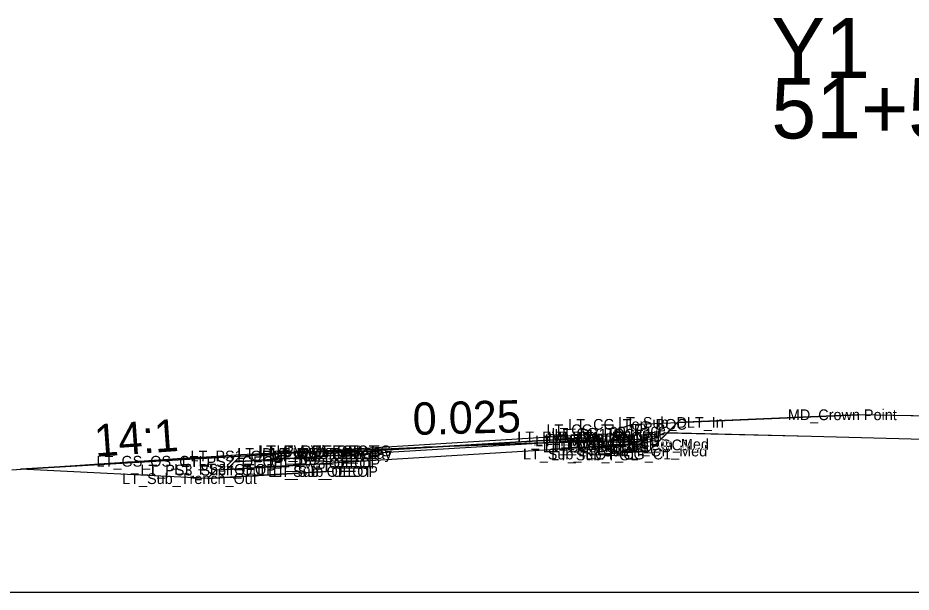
# Model space of a CAD drawing. Extents: x -26 to 2349090, y -10 to 844481.
# Drawn here: x 1105.05 to 1146.49, y 17000 to 17026.67 of the extents above; entities that cross this region are included whole.
import ezdxf

# ---------------------------------------------------------------- set-up
doc = ezdxf.new("R2010")
doc.units = 0
for name, color, linetype in [('Exist CMT Pavement', 7, 'Continuous'), ('Exist Cross Section Cell', 7, 'Continuous'), ('Exist XS Ground Line', 7, 'Continuous'), ('Prop CMT Conc Surface', 7, 'Continuous'), ('Prop CMT Concrete Structures', 7, 'Continuous'), ('Prop CMT Pvmt Course 1', 7, 'Continuous'), ('Prop CMT Pvmt Course 1 CG', 7, 'Continuous'), ('Prop CMT Pvmt Course 1 Wedge', 7, 'Continuous'), ('Prop CMT Pvmt Course 2', 7, 'Continuous'), ('Prop CMT Pvmt Course 2 Wedge', 7, 'Continuous'), ('Prop CMT Pvmt Course 3', 7, 'Continuous'), ('Prop CMT Pvmt Surface', 7, 'Continuous'), ('Prop CMT Pvmt Surface Shoulder', 7, 'Continuous'), ('Prop CMT Pvmt Wedge Surface 1', 7, 'Continuous'), ('Prop CMT Pvmt Wedge Surface 2', 7, 'Continuous'), ('Prop CMT Pvmt Wedge Surface 3', 7, 'Continuous'), ('Prop CMT Shld Paved Course 1', 7, 'Continuous'), ('Prop CMT Shld Paved Course 2', 7, 'Continuous'), ('Prop CMT Shld Paved Course 3', 7, 'Continuous'), ('Prop CMT Slope Grass', 7, 'Continuous'), ('Prop CMT Subgrade Earthwork', 7, 'Continuous'), ('Prop XS Earthwork Shape', 7, 'Continuous'), ('Prop XS SE Text', 7, 'Continuous'), ('Prop XS Side Slope Text', 7, 'Continuous'), ('Scratch_Level_0', 7, 'Continuous')]:
    doc.layers.add(name, color=color, linetype=linetype)

msp = doc.modelspace()

# ---------------------------------------------------------------- linework, layer by layer
at = {"layer": 'Exist CMT Pavement'}
for p, q in [((1128.992, 17006.91), (1129.557, 17006.929)), ((1129.557, 17006.929), (1130.183, 17006.952)), ((1130.183, 17006.952), (1131.618, 17007.006)), ((1131.618, 17007.006), (1131.999, 17007.019)), ((1119.359, 17006.56), (1121.272, 17006.629)), ((1121.272, 17006.629), (1123.909, 17006.732)), ((1123.909, 17006.732), (1124.029, 17006.737)), ((1124.029, 17006.737), (1124.071, 17006.739)), ((1124.071, 17006.739), (1124.171, 17006.742)), ((1124.171, 17006.742), (1126, 17006.812)), ((1126, 17006.812), (1126.785, 17006.837)), ((1126.785, 17006.837), (1128.992, 17006.91))]:
    msp.add_line(p, q, dxfattribs=at)
at = {"layer": 'Exist Cross Section Cell'}
msp.add_line((1000, 17000), (1150, 17000), dxfattribs=at)
at = {"layer": 'Exist XS Ground Line'}
msp.add_lwpolyline([(1104.761, 17005.674), (1106.501, 17005.798), (1107.469, 17005.865), (1109.055, 17005.967), (1110.261, 17006.052), (1112.438, 17006.199), (1112.999, 17006.236), (1113.321, 17006.258), (1115.387, 17006.392), (1115.688, 17006.414), (1116.068, 17006.429), (1116.971, 17006.467), (1117.659, 17006.498), (1118.676, 17006.535), (1121.272, 17006.629), (1124.17, 17006.742), (1126, 17006.812), (1126.785, 17006.837), (1128.992, 17006.91), (1129.557, 17006.929), (1130.183, 17006.952), (1131.618, 17007.006), (1132.283, 17007.028), (1133.624, 17007.086), (1134.488, 17007.122), (1135.06, 17007.408), (1141.871, 17007.236), (1147.653, 17007.085)], dxfattribs=at)
at = {"layer": 'Prop CMT Conc Surface'}
for p, q in [((1132.751, 17007.541), (1133.51, 17007.791)), ((1132, 17007.329), (1132.75, 17007.374)), ((1132.75, 17007.374), (1132.751, 17007.541))]:
    msp.add_line(p, q, dxfattribs=at)
at = {"layer": 'Prop CMT Concrete Structures'}
for p, q in [((1132.751, 17007.541), (1133.51, 17007.791)), ((1133.51, 17007.791), (1133.51, 17006.837)), ((1132, 17007.329), (1132.75, 17007.374)), ((1132.75, 17007.374), (1132.751, 17007.541)), ((1132, 17006.745), (1132, 17007.329)), ((1133.51, 17006.837), (1132, 17006.745))]:
    msp.add_line(p, q, dxfattribs=at)
at = {"layer": 'Prop CMT Pvmt Course 1'}
for p, q in [((1132, 17007.329), (1119.357, 17006.562)), ((1119.357, 17006.437), (1132, 17007.204)), ((1132, 17007.079), (1132, 17007.329)), ((1132, 17007.204), (1132, 17007.079)), ((1132, 17007.079), (1132, 17007.079)), ((1119.357, 17006.562), (1119.357, 17006.312)), ((1119.357, 17006.312), (1119.357, 17006.437)), ((1119.357, 17006.312), (1119.357, 17006.312))]:
    msp.add_line(p, q, dxfattribs=at)
at = {"layer": 'Prop CMT Pvmt Course 1 CG'}
for p, q in [((1132, 17006.745), (1134.01, 17006.867)), ((1132, 17006.412), (1132, 17006.745)), ((1134.324, 17006.553), (1132, 17006.412)), ((1134.01, 17006.867), (1134.324, 17006.553))]:
    msp.add_line(p, q, dxfattribs=at)
at = {"layer": 'Prop CMT Pvmt Course 1 Wedge'}
for p, q in [((1126.785, 17006.888), (1128.992, 17007.021)), ((1128.992, 17007.021), (1129.557, 17007.056)), ((1129.491, 17006.927), (1128.992, 17006.91)), ((1129.557, 17006.931), (1129.491, 17006.927)), ((1129.557, 17007.056), (1130.183, 17007.093)), ((1130.183, 17006.968), (1129.557, 17006.931)), ((1130.183, 17007.093), (1131.618, 17007.18)), ((1131.618, 17007.055), (1130.183, 17006.968)), ((1131.618, 17007.18), (1132, 17007.204)), ((1132, 17007.079), (1131.618, 17007.055)), ((1132, 17007.204), (1132, 17007.079)), ((1124.755, 17006.765), (1126, 17006.84)), ((1126, 17006.812), (1124.755, 17006.765)), ((1126, 17006.84), (1126.785, 17006.888)), ((1126.785, 17006.837), (1126, 17006.812)), ((1128.992, 17006.91), (1126.785, 17006.837))]:
    msp.add_line(p, q, dxfattribs=at)
at = {"layer": 'Prop CMT Pvmt Course 2'}
for p, q in [((1119.357, 17005.979), (1119.357, 17006.312)), ((1119.357, 17006.312), (1119.357, 17006.312)), ((1119.357, 17006.312), (1119.357, 17005.979)), ((1119.357, 17005.979), (1119.357, 17005.979))]:
    msp.add_line(p, q, dxfattribs=at)
at = {"layer": 'Prop CMT Pvmt Course 2 Wedge'}
for p, q in [((1129.491, 17006.927), (1129.557, 17006.931)), ((1129.557, 17006.929), (1129.491, 17006.927)), ((1129.557, 17006.931), (1130.183, 17006.968)), ((1130.183, 17006.952), (1129.557, 17006.929)), ((1130.183, 17006.968), (1131.618, 17007.055)), ((1131.618, 17007.006), (1130.183, 17006.952)), ((1131.618, 17007.055), (1132, 17007.079)), ((1132, 17007.019), (1131.618, 17007.006)), ((1132, 17007.079), (1132, 17007.019))]:
    msp.add_line(p, q, dxfattribs=at)
at = {"layer": 'Prop CMT Pvmt Course 3'}
for p, q in [((1119.357, 17005.979), (1119.357, 17005.979)), ((1119.357, 17005.979), (1119.357, 17005.604)), ((1119.357, 17005.604), (1119.357, 17005.979)), ((1119.357, 17005.604), (1119.357, 17005.604))]:
    msp.add_line(p, q, dxfattribs=at)
at = {"layer": 'Prop CMT Pvmt Surface'}
msp.add_line((1132, 17007.329), (1119.357, 17006.562), dxfattribs=at)
at = {"layer": 'Prop CMT Pvmt Surface Shoulder'}
msp.add_line((1119.357, 17006.562), (1115.357, 17006.32), dxfattribs=at)
at = {"layer": 'Prop CMT Pvmt Wedge Surface 1'}
for p, q in [((1132, 17007.204), (1119.357, 17006.437)), ((1132, 17007.329), (1132, 17007.204)), ((1132, 17007.204), (1132, 17007.204)), ((1119.357, 17006.437), (1119.357, 17006.562)), ((1119.357, 17006.437), (1119.357, 17006.437))]:
    msp.add_line(p, q, dxfattribs=at)
at = {"layer": 'Prop CMT Pvmt Wedge Surface 2'}
for p, q in [((1132, 17007.079), (1119.357, 17006.312)), ((1132, 17007.329), (1132, 17007.079)), ((1119.357, 17006.312), (1119.357, 17006.562))]:
    msp.add_line(p, q, dxfattribs=at)
at = {"layer": 'Prop CMT Pvmt Wedge Surface 3'}
for p, q in [((1132, 17007.329), (1132, 17006.745)), ((1132, 17006.745), (1119.357, 17005.979)), ((1119.357, 17005.979), (1119.357, 17006.562))]:
    msp.add_line(p, q, dxfattribs=at)
at = {"layer": 'Prop CMT Shld Paved Course 1'}
for p, q in [((1119.357, 17006.562), (1115.357, 17006.32)), ((1119.357, 17006.312), (1119.357, 17006.562)), ((1115.357, 17006.32), (1115.091, 17006.054)), ((1115.091, 17006.054), (1119.357, 17006.312))]:
    msp.add_line(p, q, dxfattribs=at)
at = {"layer": 'Prop CMT Shld Paved Course 2'}
for p, q in [((1119.357, 17006.312), (1115.091, 17006.054)), ((1119.357, 17005.979), (1119.357, 17006.312)), ((1115.091, 17006.054), (1114.736, 17005.699)), ((1114.736, 17005.699), (1119.357, 17005.979))]:
    msp.add_line(p, q, dxfattribs=at)
at = {"layer": 'Prop CMT Shld Paved Course 3'}
for p, q in [((1114.736, 17005.699), (1114.236, 17005.669)), ((1119.357, 17005.979), (1114.736, 17005.699)), ((1119.357, 17005.604), (1119.357, 17005.979)), ((1114.236, 17005.669), (1113.837, 17005.27)), ((1113.837, 17005.27), (1119.357, 17005.604))]:
    msp.add_line(p, q, dxfattribs=at)
at = {"layer": 'Prop CMT Slope Grass'}
for p, q in [((1133.51, 17007.791), (1144, 17008.236)), ((1154.49, 17008.027), (1144, 17008.236)), ((1115.357, 17006.32), (1105.175, 17005.703))]:
    msp.add_line(p, q, dxfattribs=at)
at = {"layer": 'Prop CMT Subgrade Earthwork'}
for p, q in [((1135.653, 17007.882), (1134.324, 17006.553)), ((1132, 17007.329), (1132, 17006.412)), ((1119.357, 17005.604), (1119.359, 17006.56)), ((1132, 17006.412), (1134.324, 17006.553)), ((1113.837, 17005.27), (1105.175, 17005.703)), ((1119.357, 17005.604), (1113.837, 17005.27)), ((1119.357, 17005.604), (1119.357, 17005.604))]:
    msp.add_line(p, q, dxfattribs=at)
at = {"layer": 'Prop XS Earthwork Shape'}
for points in [[(1149.041, 17006.837), (1150, 17006.848), (1151.605, 17006.87), (1152.325, 17006.883), (1153.396, 17006.913), (1152.238, 17008.072), (1144, 17008.236), (1135.653, 17007.882), (1135.177, 17007.405), (1141.871, 17007.236), (1147.653, 17007.085), (1148.365, 17006.841)], [(1132.283, 17007.028), (1133.624, 17007.086), (1134.488, 17007.122), (1135.06, 17007.408), (1135.177, 17007.405), (1134.324, 17006.553), (1132, 17006.412), (1131.999, 17007.019)], [(1119.357, 17005.604), (1113.837, 17005.27), (1105.175, 17005.703), (1115.357, 17006.32), (1119.357, 17006.562)], [(1116.971, 17006.467), (1117.659, 17006.498), (1118.676, 17006.535), (1119.357, 17006.562), (1115.357, 17006.32), (1105.175, 17005.703), (1106.501, 17005.798), (1107.469, 17005.865), (1109.055, 17005.967), (1110.261, 17006.052), (1112.438, 17006.199), (1112.999, 17006.236), (1113.321, 17006.258), (1115.387, 17006.392), (1115.688, 17006.414), (1116.068, 17006.429)], [(1123.909, 17006.732), (1124.029, 17006.737), (1124.071, 17006.739), (1124.171, 17006.742)]]:
    msp.add_lwpolyline(points, close=True, dxfattribs=at)

# ---------------------------------------------------------------- texts
at = {"layer": 'Exist Cross Section Cell'}
for s, p in [('Y1', (1140, 17023.866)), ('51+50.00 / 1', (1140, 17021.066))]:
    msp.add_text(s, height=2.8, dxfattribs=at).set_placement(p)
at = {"layer": 'Prop XS SE Text'}
msp.add_text('0.025', height=1.5, rotation=1.4321, dxfattribs=at).set_placement((1123.381, 17007.299))
at = {"layer": 'Prop XS Side Slope Text'}
msp.add_text('14:1', height=1.5, rotation=4.0856, dxfattribs=at).set_placement((1108.644, 17006.28))
at = {"layer": 'Scratch_Level_0'}
for s, p in [('MD_Crown Point', (1140.768, 17007.986)), ('LT_CG_Top_Face', (1129.566, 17007.291)), ('LT_CG_Top_BOC', (1130.581, 17007.541)), ('LT_Sub_DLT_In', (1132.89, 17007.632)), ('LT_PV1_Overlay_Null', (1128.217, 17006.954)), ('LT_PV2_IEEOP', (1129.488, 17006.829)), ('LT_PV1_IEEOP', (1129.63, 17006.954)), ('LT_PV2_PGL', (1129.803, 17006.829)), ('LT_CG_Top_Gut', (1129.809, 17007.124)), ('LT_PV1_PGL', (1129.945, 17007.079)), ('LT_PV_IEEOP_EG', (1129.046, 17006.769)), ('LT_CG_Bot_IE1', (1129.406, 17006.495)), ('LT_PV3_IEEOP', (1129.488, 17006.495)), ('LT_PV3_PGL', (1129.803, 17006.495)), ('LT_CG1_Shelf_In_Med', (1130.081, 17006.617)), ('LT_CG_Bot_BOC1', (1130.506, 17006.587)), ('LT_PS1_OEOP', (1113.058, 17006.07)), ('LT_PV1_OEOT Overlay', (1115.227, 17006.187)), ('LT_Sub Tie Out', (1116.193, 17006.31)), ('LT_PV_OEEOP_EG', (1116.245, 17006.31)), ('LT_PV2_OEEOP', (1116.684, 17006.062)), ('LT_PV1_OEEOP', (1116.826, 17006.187)), ('LT_PV2_OEOT', (1116.901, 17006.062)), ('LT_PV1_OEOT', (1117.042, 17006.312)), ('LT_Sub_IEOT_CG_C1', (1128.48, 17006.162)), ('LT_Sub_PGL', (1129.78, 17006.12)), ('LT_Sub_IEOP_Med', (1131.041, 17006.303)), ('LT_GS_OS_CTL', (1108.7, 17005.828)), ('LT_PS2_OEOP', (1112.65, 17005.804)), ('LT_PV3_OEEOP', (1116.684, 17005.729)), ('LT_PV3_OEOT', (1116.901, 17005.729)), ('LT_PS3_Shelf_Out', (1110.732, 17005.419)), ('LT_PS3_OEOP', (1112.295, 17005.449)), ('LT_Sub_OEEOP', (1116.66, 17005.354)), ('LT_Sub_OEOT', (1116.877, 17005.354)), ('LT_Sub_Trench_Out', (1109.888, 17005.02))]:
    msp.add_text(s, height=0.5, dxfattribs=at).set_placement(p)

doc.saveas('drawing.dxf')
